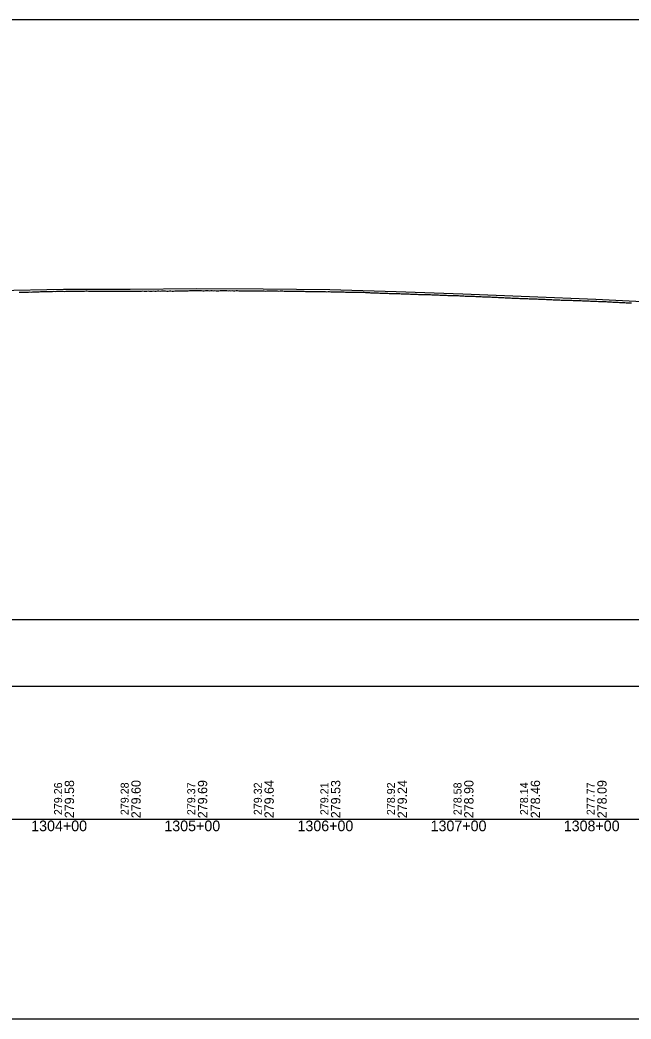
# Model space of a CAD drawing. Extents: x -3627 to 47473, y 2850 to 4350.
# Drawn here: x 17745 to 18204, y 2850 to 3600 of the extents above; entities that cross this region are included whole.
import ezdxf

# ---------------------------------------------------------------- set-up
doc = ezdxf.new("R2010")
doc.units = 0
for name, color, linetype in [('RD_DDB_Profile_EX', 7, 'Continuous'), ('RD_DDB_Profile_PR', 7, 'Continuous'), ('RD_DDB_StaTX', 7, 'Continuous'), ('RD_DDB_StripGrade', 7, 'Continuous'), ('RD_GPK_Profile_Cell', 7, 'Continuous'), ('RD_SHT_ShtClip', 7, 'Continuous')]:
    doc.layers.add(name, color=color, linetype=linetype)

msp = doc.modelspace()

# ---------------------------------------------------------------- linework, layer by layer
at = {"layer": 'RD_DDB_Profile_EX'}
for points in [[(17744.044335, 3395.63508), (17745.045291, 3395.634065), (17746.052638, 3395.678835), (17747.053582, 3395.689415), (17748.048622, 3395.695505), (17749.049565, 3395.744595), (17750.051496, 3395.749455), (17751.053058, 3395.748775), (17752.047493, 3395.8048), (17753.049058, 3395.766145), (17754.050991, 3395.809275), (17755.049182, 3395.892725), (17756.05176, 3395.95387), (17757.052662, 3395.95913), (17758.054585, 3396.01437)], [(17758.054585, 3396.01437), (17759.049709, 3396.01458), (17760.0506, 3396.09543), (17761.057285, 3396.139575), (17762.051372, 3396.15222), (17763.053302, 3396.151285), (17764.054173, 3396.150495), (17765.049326, 3396.200735), (17766.051262, 3396.1998), (17767.056871, 3396.243965), (17768.058791, 3396.255565), (17769.052897, 3396.24338), (17770.054823, 3396.29239), (17771.055665, 3396.285175), (17772.050863, 3396.29817), (17773.052795, 3396.303665), (17774.058362, 3396.34764), (17775.053565, 3396.34788), (17776.054403, 3396.290665), (17777.056325, 3396.3267), (17778.057847, 3396.282515), (17779.05238, 3396.34563), (17780.059024, 3396.395875), (17781.060545, 3396.395275), (17782.055081, 3396.388795), (17783.055889, 3396.33797), (17784.057808, 3396.386985), (17785.051953, 3396.400645), (17786.058587, 3396.400875), (17787.060506, 3396.443345), (17788.054653, 3396.457015), (17789.056578, 3396.462905), (17790.05471, 3396.464025), (17791.057353, 3396.5001), (17792.055489, 3396.494815), (17793.057408, 3396.48726), (17794.056669, 3396.562345), (17795.058591, 3396.554515), (17796.057445, 3396.519695), (17797.059368, 3396.468535), (17798.053908, 3396.46204), (17799.060547, 3396.45581), (17800.055084, 3396.412445), (17801.060613, 3396.41297), (17802.055145, 3396.406525), (17803.054385, 3396.37113), (17804.056319, 3396.432965), (17805.055553, 3396.434375), (17806.056387, 3396.33996), (17807.055628, 3396.39769), (17808.057558, 3396.39675), (17809.052078, 3396.34681), (17810.058727, 3396.397065), (17811.052148, 3396.39728), (17812.058802, 3396.35394), (17813.053313, 3396.3168), (17814.059969, 3396.360625), (17815.054476, 3396.32344), (17816.053298, 3396.33092), (17817.05524, 3396.35491), (17818.049739, 3396.39864), (17819.056398, 3396.367855), (17820.050893, 3396.31791), (17821.05648, 3396.361955), (17822.050971, 3396.399445), (17823.05292, 3396.361175), (17824.054869, 3396.353935), (17825.056818, 3396.409505), (17826.057655, 3396.45229), (17827.052185, 3396.408855), (17828.054134, 3396.40802), (17829.056083, 3396.493925), (17830.056892, 3396.493125), (17831.058831, 3396.45565), (17832.06077, 3396.454815), (17833.062708, 3396.483405), (17834.064647, 3396.482395), (17835.058067, 3396.525715), (17836.060006, 3396.531605), (17837.062703, 3396.544825), (17838.064648, 3396.48686), (17839.066594, 3396.50017), (17840.067315, 3396.527945), (17841.06925, 3396.555215), (17842.063903, 3396.52698), (17843.064606, 3396.533435), (17844.067334, 3396.525355), (17845.06468, 3396.573095), (17846.066628, 3396.402185), (17847.067284, 3396.47884), (17848.069222, 3396.56263), (17849.07116, 3396.56926), (17850.06458, 3396.53484), (17851.067353, 3396.568705), (17852.069298, 3396.60992), (17853.069907, 3396.57472), (17854.071841, 3396.56589), (17855.073775, 3396.514885), (17856.075709, 3396.529895), (17857.06913, 3396.622105), (17858.076478, 3396.572535)], [(17858.076478, 3396.572535), (17859.078412, 3396.529615), (17860.071833, 3396.53783), (17861.073767, 3396.595075), (17862.075702, 3396.67805), (17863.075035, 3396.629155), (17864.07647, 3396.628655), (17865.078404, 3396.685915), (17866.073213, 3396.72779), (17867.07376, 3396.710695), (17868.080221, 3396.719095), (17869.075036, 3396.71912), (17870.076973, 3396.759935), (17871.071282, 3396.785035), (17872.07774, 3396.793415), (17873.079677, 3396.79265), (17874.073098, 3396.818085), (17875.075036, 3396.81714), (17876.076973, 3396.824555), (17877.075802, 3396.84258), (17878.07774, 3396.84181), (17879.079677, 3396.84104), (17880.074525, 3396.882675), (17881.07954, 3396.833025), (17882.081471, 3396.782195), (17883.077233, 3396.765615), (17884.07774, 3396.79797), (17885.079677, 3396.796905), (17886.07903, 3396.831945), (17887.080444, 3396.78996), (17888.082381, 3396.83919), (17889.075802, 3396.82234), (17890.07774, 3396.780025), (17891.08416, 3396.830195), (17892.078506, 3396.78912), (17893.080444, 3396.77976), (17894.082381, 3396.778935), (17895.080284, 3396.82156), (17896.083148, 3396.846715), (17897.085085, 3396.88734), (17898.078506, 3396.820205), (17899.080444, 3396.810605), (17900.086312, 3396.819915), (17901.08121, 3396.78727), (17902.083148, 3396.82777), (17903.076568, 3396.76924), (17904.079454, 3396.809815), (17905.085852, 3396.768755), (17906.079272, 3396.73643), (17907.08121, 3396.81807), (17908.084104, 3396.80857), (17909.081976, 3396.768675), (17910.083914, 3396.782535), (17911.085852, 3396.772535), (17912.079272, 3396.74052), (17913.082173, 3396.75754), (17914.087043, 3396.716815), (17915.081976, 3396.71682), (17916.083914, 3396.706995), (17917.085294, 3396.697535), (17918.080242, 3396.747545), (17919.086618, 3396.738785), (17920.087022, 3396.660945), (17921.082948, 3396.670265), (17922.084892, 3396.62813), (17923.089723, 3396.628595), (17924.08468, 3396.646645), (17925.086055, 3396.587075), (17926.081017, 3396.58708), (17927.087384, 3396.587285), (17928.089322, 3396.58622), (17929.082742, 3396.53646), (17930.08468, 3396.61283), (17931.091038, 3396.60387), (17932.086014, 3396.60387), (17933.086391, 3396.643955), (17934.086778, 3396.60452), (17935.088719, 3396.55357), (17936.090661, 3396.54341), (17937.084081, 3396.552835), (17938.090432, 3396.58464), (17939.085417, 3396.52139), (17940.087363, 3396.570555), (17941.087723, 3396.61062), (17942.087128, 3396.56168), (17943.090069, 3396.45176), (17944.092014, 3396.460135), (17945.085433, 3396.460335), (17946.091771, 3396.4698), (17947.086776, 3396.4919), (17948.088725, 3396.459605), (17949.089069, 3396.44951), (17950.088477, 3396.350635), (17951.090419, 3396.36847), (17952.086451, 3396.368695), (17953.091182, 3396.35969), (17954.093125, 3396.349375), (17955.088149, 3396.358785), (17956.090102, 3396.398415), (17957.09481, 3396.33936), (17958.08984, 3396.348805)], [(17958.08984, 3396.348805), (17959.091786, 3396.285885), (17960.086827, 3396.276365), (17961.092546, 3396.21744), (17962.094493, 3396.235655), (17963.089536, 3396.159415), (17964.091493, 3396.14657), (17965.096167, 3396.1661), (17966.091217, 3396.156525), (17967.093167, 3396.1845), (17968.088227, 3396.13449), (17969.09289, 3396.12519), (17970.095875, 3396.10356), (17971.090938, 3396.093905), (17972.091243, 3396.13371), (17973.097539, 3396.133835), (17974.092609, 3396.074145), (17975.092902, 3396.02355), (17976.089025, 3396.06405), (17977.095318, 3396.0642), (17978.095608, 3396.013555), (17979.090688, 3395.97329), (17980.093697, 3395.97273), (17981.098313, 3395.892585), (17982.093397, 3395.82304), (17983.095351, 3395.86243), (17984.089823, 3395.89327), (17985.096106, 3395.89344), (17986.09806, 3395.862165), (17987.091477, 3395.872185), (17988.093431, 3395.81151), (17989.099088, 3395.7621), (17990.094186, 3395.702235), (17991.09614, 3395.671595), (17992.089557, 3395.71143), (17993.096895, 3395.71182), (17994.091997, 3395.68219), (17995.09659, 3395.65231), (17996.091688, 3395.611375), (17997.097966, 3395.581145), (17998.092441, 3395.621555), (17999.094398, 3395.580935), (18000.093813, 3395.581425), (18001.094092, 3395.57126), (18002.094563, 3395.552455), (18003.094849, 3395.54219), (18004.094267, 3395.43324), (18005.096222, 3395.422715), (18006.090689, 3395.41336), (18007.096976, 3395.333005), (18008.092058, 3395.282995), (18009.096684, 3395.21385), (18010.091761, 3395.21384), (18011.099097, 3395.17393), (18012.092513, 3395.174105), (18013.087584, 3395.13378), (18014.093877, 3395.10489), (18015.088328, 3395.02464), (18016.094627, 3395.01515), (18017.089688, 3395.00551), (18018.094344, 3394.99628), (18019.089401, 3394.85588), (18020.090753, 3394.845795), (18021.090147, 3394.83738), (18022.091502, 3394.746465), (18023.089267, 3394.747845), (18024.092252, 3394.74714), (18025.091038, 3394.68934), (18026.093001, 3394.638295), (18027.087434, 3394.58882), (18028.092133, 3394.58925), (18029.088179, 3394.53953), (18030.09289, 3394.56172), (18031.088923, 3394.51205), (18032.089276, 3394.398885), (18033.083705, 3394.35879), (18034.090028, 3394.30896), (18035.09139, 3394.31794), (18036.084806, 3394.30871), (18037.08778, 3394.30805), (18038.093505, 3394.2181), (18039.08853, 3394.14925), (18040.089892, 3394.158225), (18041.090227, 3394.157525), (18042.090644, 3394.068255), (18043.090986, 3394.067605), (18044.085422, 3394.03688), (18045.087376, 3393.986155), (18046.088729, 3393.976285), (18047.088131, 3393.977205), (18048.089487, 3393.92682), (18049.089812, 3393.9167), (18050.08588, 3393.916925), (18051.090577, 3393.848315), (18052.086633, 3393.808035), (18053.08799, 3393.7981), (18054.088314, 3393.73783), (18055.088745, 3393.70821), (18056.089077, 3393.66702), (18057.090424, 3393.61897), (18058.085468, 3393.547545)], [(18058.085468, 3393.547545), (18059.086817, 3393.537525), (18060.093128, 3393.487705), (18061.087578, 3393.44773), (18062.087892, 3393.42788), (18063.083972, 3393.387715), (18064.084287, 3393.37735), (18065.091631, 3393.32784), (18066.091934, 3393.26741), (18067.094911, 3393.266605), (18068.088332, 3393.195775), (18069.091317, 3393.16446), (18070.091603, 3393.194375), (18071.093537, 3393.17386), (18072.094863, 3393.12336), (18073.089955, 3393.083155), (18074.090215, 3393.052115), (18075.093219, 3392.96139), (18076.093462, 3393.000825), (18077.08965, 3392.92092), (18078.089893, 3392.83045), (18079.091827, 3392.779455), (18080.093137, 3392.759175), (18081.099397, 3392.76936), (18082.092821, 3392.729385), (18083.095838, 3392.688765), (18084.096046, 3392.618425), (18085.09907, 3392.60773), (18086.092493, 3392.547765), (18087.094419, 3392.46627), (18088.095715, 3392.4658), (18089.097638, 3392.38534), (18090.09956, 3392.384415), (18091.094105, 3392.29522), (18092.096033, 3392.24435), (18093.09732, 3392.24397), (18094.099246, 3392.193105), (18095.099385, 3392.13196), (18096.095732, 3392.08221), (18097.095872, 3392.071), (18098.102082, 3392.060625), (18099.103354, 3391.981265), (18100.09857, 3391.931235), (18101.099844, 3391.83084), (18102.101762, 3391.82992), (18103.095187, 3391.81951), (18104.102541, 3391.69114), (18105.095966, 3391.630755), (18106.096611, 3391.56107), (18107.096746, 3391.560305), (18108.097384, 3391.572235), (18109.097525, 3391.53201), (18110.096387, 3391.443955), (18111.102611, 3391.383695), (18112.097167, 3391.313455), (18113.096658, 3391.29402), (18114.097946, 3391.224485), (18115.097435, 3391.196105), (18116.097606, 3391.164555), (18117.096477, 3391.116295), (18118.091636, 3391.10606), (18119.097261, 3391.0365), (18120.092413, 3391.00681), (18121.098045, 3390.977835), (18122.09319, 3390.92781), (18123.092046, 3390.919425), (18124.092255, 3390.90857), (18125.092823, 3390.81014), (18126.093039, 3390.809315), (18127.0936, 3390.730795), (18128.087024, 3390.690955), (18129.092695, 3390.6416), (18130.087802, 3390.591585), (18131.093479, 3390.592225), (18132.088579, 3390.58235), (18133.087434, 3390.5547), (18134.089356, 3390.50355), (18135.088212, 3390.415215), (18136.088473, 3390.37415), (18137.088989, 3390.356275), (18138.089257, 3390.3054), (18139.089766, 3390.30706), (18140.08319, 3390.25732), (18141.086163, 3390.256495), (18142.090824, 3390.16662), (18143.085299, 3390.11717), (18144.087217, 3390.03544), (18145.088542, 3390.02527), (18146.083616, 3390.025255), (18147.089915, 3389.94483), (18148.090178, 3389.894135), (18149.085258, 3389.88438), (18150.087176, 3389.843205), (18151.089094, 3389.75286), (18152.084193, 3389.7627), (18153.090476, 3389.762885), (18154.090716, 3389.68184), (18155.092628, 3389.620915), (18156.087743, 3389.570895), (18157.089665, 3389.609855), (18158.095932, 3389.59004)], [(18158.095932, 3389.59004), (18159.089357, 3389.560285), (18160.091273, 3389.50919), (18161.093188, 3389.467695), (18162.088329, 3389.377765), (18163.094585, 3389.318345), (18164.096504, 3389.317305), (18165.089929, 3389.347265), (18166.091848, 3389.306305), (18167.093766, 3389.255205), (18168.09325, 3389.23608), (18169.095172, 3389.184865), (18170.097095, 3389.164555), (18171.090519, 3389.1045), (18172.092441, 3389.04305), (18173.094364, 3389.0023), (18174.093852, 3388.90354), (18175.095778, 3388.912835), (18176.095929, 3388.922495), (18177.091127, 3388.872465), (18178.093053, 3388.79248), (18179.099266, 3388.700645), (18180.094474, 3388.661105), (18181.096403, 3388.73116), (18182.09653, 3388.68047), (18183.099606, 3388.66919), (18184.093685, 3388.66885), (18185.095614, 3388.57857), (18186.098211, 3388.527095), (18187.100145, 3388.465295), (18188.095416, 3388.415255), (18189.10041, 3388.36508), (18190.10234, 3388.26408), (18191.104271, 3388.224075), (18192.098374, 3388.179665), (18193.100308, 3388.139565), (18194.104141, 3388.06044), (18195.104872, 3387.997875), (18196.10681, 3387.985525), (18197.100934, 3387.935095), (18198.102876, 3387.818075), (18199.104817, 3387.81713), (18200.105515, 3387.74284), (18201.105058, 3387.70543), (18202.10896, 3387.69261), (18203.109658, 3387.62957), (18204.1116, 3387.601755)]]:
    msp.add_lwpolyline(points, dxfattribs=at)
at = {"layer": 'RD_DDB_Profile_PR'}
msp.add_lwpolyline([(17727.33, 3396.808), (17777.33, 3397.9145), (17827.33, 3398.0085), (17877.33, 3398.4425), (17927.33, 3398.187), (17977.33, 3397.6525), (18027.33, 3396.189), (18077.33, 3394.499), (18127.33, 3392.3215), (18177.33, 3390.4535), (18227.33, 3387.8265), (18277.33, 3384.6625), (18327.33, 3381.561), (18377.33, 3378.3055), (18427.33, 3375.2705), (18477.33, 3371.9105), (18527.33, 3368.8045), (18577.33, 3365.8225), (18627.33, 3362.71), (18677.33, 3359.498)], dxfattribs=at)
at = {"layer": 'RD_GPK_Profile_Cell'}
msp.add_line((1000, 3000), (46705.077602, 3000), dxfattribs=at)
at = {"layer": 'RD_SHT_ShtClip'}
for points in [[(17453.33, 3600), (17453.33, 3100), (18953.33, 3100), (18953.33, 3100), (18953.33, 3600), (18953.33, 3600)], [(17433.33, 3150), (18973.33, 3150), (18973.33, 2850), (17433.33, 2850)]]:
    msp.add_lwpolyline(points, close=True, dxfattribs=at)

# ---------------------------------------------------------------- texts
at = {"layer": 'RD_DDB_StaTX'}
for s, p in [('1304+00', (17753.125471, 2991)), ('1305+00', (17853.125471, 2991)), ('1306+00', (17953.125471, 2991)), ('1307+00', (18053.125471, 2991)), ('1308+00', (18153.125471, 2991))]:
    msp.add_text(s, height=8, dxfattribs=at).set_placement(p)
at = {"layer": 'RD_DDB_StripGrade'}
for s, height, p in [('279.26', 6, (17776.33, 3003.073688)), ('279.58', 7, (17785.33, 3000.75)), ('279.28', 6, (17826.33, 3003.073688)), ('279.60', 7, (17835.33, 3000.75)), ('279.37', 6, (17876.33, 3003.073688)), ('279.69', 7, (17885.33, 3000.75)), ('279.32', 6, (17926.33, 3003.073688)), ('279.64', 7, (17935.33, 3000.75)), ('279.21', 6, (17976.33, 3003.073688)), ('279.53', 7, (17985.33, 3000.75)), ('278.92', 6, (18026.33, 3003.073688)), ('279.24', 7, (18035.33, 3000.75)), ('278.58', 6, (18076.33, 3003.073688)), ('278.90', 7, (18085.33, 3000.75)), ('278.14', 6, (18126.33, 3003.073688)), ('278.46', 7, (18135.33, 3000.75)), ('277.77', 6, (18176.33, 3003.073688)), ('278.09', 7, (18185.33, 3000.75))]:
    msp.add_text(s, height=height, rotation=90, dxfattribs=at).set_placement(p)

doc.saveas('drawing.dxf')
